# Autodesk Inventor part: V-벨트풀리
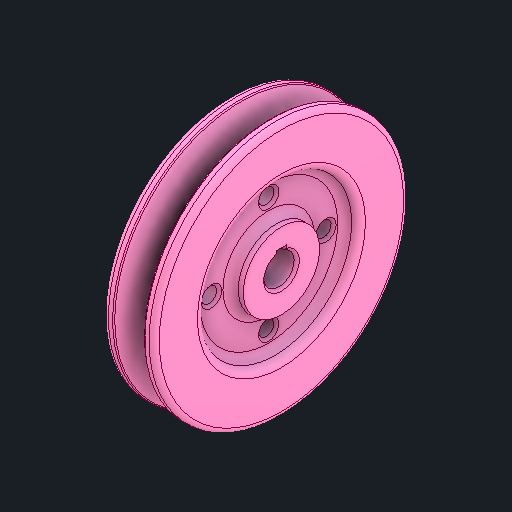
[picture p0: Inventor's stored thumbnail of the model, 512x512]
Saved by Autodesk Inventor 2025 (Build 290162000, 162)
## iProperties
Created: 2025-08
Part Number: V-벨트풀리
Material: 강철, 연강
Document SubType Name: Modeling
Designer: infra012
Density: 7.86 g/cm^3
Appearance: 기본값
Author: jhkim
Sending System: Autodesk Inventor 2026
Preprocessor: ST-DEVELOPER v20.1
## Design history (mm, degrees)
sketch "스케치1"
  geometry: 1 further point
  constraints: 1 other
feature "솔리드1"
node "솔리드2"
